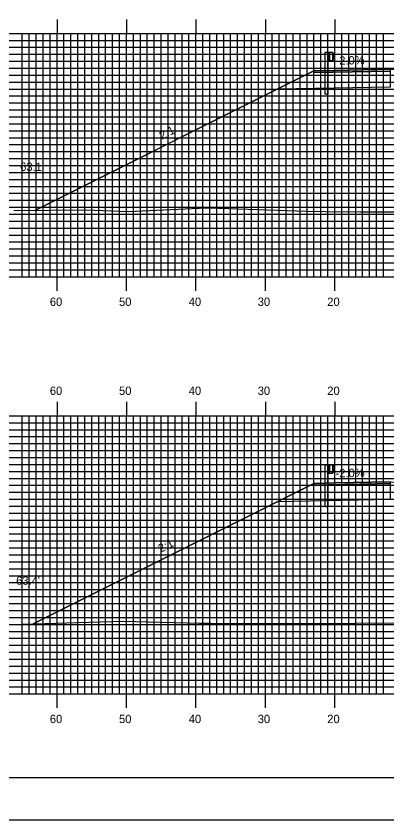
# Model space of a CAD drawing. Extents: x 1812554 to 1812897, y 442591 to 442811.
# Drawn here: x 1812654 to 1812707.4, y 442590.5 to 442706.2 of the extents above; entities that cross this region are included whole.
import ezdxf

# ---------------------------------------------------------------- set-up
doc = ezdxf.new("R2010")
doc.units = 0
for name, color, linetype in [('ANNOTATION', 7, 'Continuous'), ('BORDER', 7, 'Continuous'), ('D_Guardrail_Beam_Lt', 7, 'Continuous'), ('D_Roadway_Centerline', 7, 'Continuous'), ('D_Roadway_Edge_Shoulder', 7, 'Continuous'), ('D_Roadway_SlopeLines', 7, 'Continuous'), ('D_Roadway_SubGrade', 7, 'Continuous'), ('D_Text_Standard', 7, 'Continuous'), ('H_V ANNOTATION', 7, 'Continuous'), ('MAJOR', 7, 'Continuous'), ('MINOR', 7, 'Continuous'), ('PLOT BOUNDARY', 7, 'Continuous'), ('S_Roadway_Centerline', 7, 'Continuous')]:
    doc.layers.add(name, color=color, linetype=linetype)

msp = doc.modelspace()

# ---------------------------------------------------------------- linework, layer by layer
at = {"layer": 'BORDER'}
msp.add_lwpolyline([(1812570.34, 442596.67), (1812890.34, 442596.67), (1812890.34, 442806.67), (1812570.34, 442806.67)], close=True, dxfattribs=at)
at = {"layer": 'D_Guardrail_Beam_Lt'}
for p, q in [((1812698.51, 442700.93), (1812698.51, 442694.93)), ((1812698.98, 442700.93), (1812698.51, 442700.93)), ((1812699.67, 442700.93), (1812698.98, 442700.93)), ((1812698.98, 442700.93), (1812698.98, 442699.76)), ((1812699.05, 442700.93), (1812699.05, 442699.76)), ((1812699.15, 442700.93), (1812699.15, 442699.76)), ((1812699.67, 442699.76), (1812699.67, 442700.93)), ((1812699.67, 442700.84), (1812699.75, 442700.83)), ((1812699.76, 442700.82), (1812699.9, 442700.72)), ((1812698.98, 442699.76), (1812699.67, 442699.76)), ((1812699, 442694.93), (1812699, 442699.76)), ((1812699.75, 442699.86), (1812699.67, 442699.84)), ((1812699.68, 442700.38), (1812699.68, 442700.31)), ((1812699.9, 442700.58), (1812699.71, 442700.44)), ((1812699.71, 442700.25), (1812699.9, 442700.11)), ((1812699.9, 442699.97), (1812699.76, 442699.87)), ((1812699, 442694.93), (1812698.51, 442694.93)), ((1812698.51, 442641.59), (1812698.51, 442635.59)), ((1812698.98, 442641.59), (1812698.51, 442641.59)), ((1812699.67, 442641.59), (1812698.98, 442641.59)), ((1812698.98, 442641.59), (1812698.98, 442640.43)), ((1812699.05, 442641.59), (1812699.05, 442640.43)), ((1812699.15, 442641.59), (1812699.15, 442640.43)), ((1812699.67, 442640.43), (1812699.67, 442641.59)), ((1812699.67, 442641.51), (1812699.75, 442641.49)), ((1812699.75, 442640.52), (1812699.67, 442640.51)), ((1812699.68, 442641.04), (1812699.68, 442640.97)), ((1812699.9, 442641.24), (1812699.71, 442641.11)), ((1812699.71, 442640.91), (1812699.9, 442640.77)), ((1812699.76, 442641.49), (1812699.9, 442641.39)), ((1812699.9, 442640.63), (1812699.76, 442640.53)), ((1812698.98, 442640.43), (1812699.67, 442640.43)), ((1812699, 442635.59), (1812699, 442640.43)), ((1812699, 442635.59), (1812698.51, 442635.59))]:
    msp.add_line(p, q, dxfattribs=at)
for centre, major_axis, start_param, end_param in [((1812699.74, 442700.79), (0.0417, 0), 0.959931, 1.376053), ((1812699.85, 442700.65), (0.0877, 0), 5.323254, 7.243116), ((1812699.75, 442700.38), (-0.0789, 0), 5.323254, 6.283185), ((1812699.75, 442700.31), (-0.0789, 0), 6.283185, 7.243116), ((1812699.74, 442699.9), (0.0417, 0), 4.907132, 5.323254), ((1812699.85, 442700.04), (0.0877, 0), 5.323254, 7.243116), ((1812699.75, 442641.04), (-0.0789, 0), 5.323254, 6.283185), ((1812699.75, 442640.97), (-0.0789, 0), 6.283185, 7.243116), ((1812699.74, 442641.45), (0.0417, 0), 0.959931, 1.376053), ((1812699.74, 442640.56), (0.0417, 0), 4.907132, 5.323254), ((1812699.85, 442641.32), (0.0877, 0), 5.323254, 7.243116), ((1812699.85, 442640.7), (0.0877, 0), 5.323254, 7.243116)]:
    msp.add_ellipse(centre, major_axis=major_axis, ratio=0.995501, start_param=start_param, end_param=end_param, dxfattribs=at)
at = {"layer": 'D_Roadway_Centerline'}
for points in [[(1812656.82, 442678.23), (1812691.73, 442695.68), (1812696.94, 442698.28), (1812699.94, 442698.34), (1812707.94, 442698.5), (1812719.94, 442697.93), (1812731.94, 442697.35), (1812739.94, 442696.97), (1812742.94, 442696.82), (1812748.47, 442694.06), (1812784.48, 442676.06)], [(1812656.53, 442618.74), (1812691.73, 442636.34), (1812696.94, 442638.95), (1812699.94, 442639.01), (1812707.94, 442639.17), (1812719.94, 442638.59), (1812731.94, 442638.02), (1812739.94, 442637.63), (1812742.94, 442637.49), (1812748.47, 442634.72), (1812777.24, 442620.34)]]:
    msp.add_lwpolyline(points, dxfattribs=at)
at = {"layer": 'D_Roadway_Edge_Shoulder'}
for points in [[(1812707.94, 442698.5), (1812699.94, 442698.34), (1812699.94, 442698.34), (1812696.94, 442698.28), (1812696.94, 442698.03), (1812707.94, 442698.25)], [(1812707.94, 442639.17), (1812699.94, 442639.01), (1812699.94, 442639.01), (1812696.94, 442638.95), (1812696.94, 442638.7), (1812707.94, 442638.92)]]:
    msp.add_lwpolyline(points, close=True, dxfattribs=at)
at = {"layer": 'D_Roadway_SlopeLines'}
for points in [[(1812696.94, 442698.28), (1812656.82, 442678.23)], [(1812696.94, 442638.95), (1812656.53, 442618.74)]]:
    msp.add_lwpolyline(points, dxfattribs=at)
at = {"layer": 'D_Roadway_SubGrade'}
for points in [[(1812707.94, 442697.84), (1812707.94, 442698.25), (1812696.94, 442698.03), (1812696.94, 442698.28), (1812691.73, 442695.68), (1812707.94, 442696)], [(1812707.94, 442638.5), (1812707.94, 442638.92), (1812696.94, 442638.7), (1812696.94, 442638.95), (1812691.73, 442636.34), (1812707.94, 442636.67)]]:
    msp.add_lwpolyline(points, close=True, dxfattribs=at)
at = {"layer": 'MAJOR'}
for p, q in [((1812659.94, 442705.67), (1812659.94, 442703.67)), ((1812669.94, 442705.67), (1812669.94, 442703.67)), ((1812679.94, 442705.67), (1812679.94, 442703.67)), ((1812689.94, 442705.67), (1812689.94, 442703.67)), ((1812699.94, 442705.67), (1812699.94, 442703.67)), ((1812579.94, 442703.67), (1812859.94, 442703.67)), ((1812579.94, 442703.67), (1812859.94, 442703.67)), ((1812659.94, 442668.67), (1812659.94, 442703.67)), ((1812669.94, 442668.67), (1812669.94, 442703.67)), ((1812679.94, 442668.67), (1812679.94, 442703.67)), ((1812689.94, 442668.67), (1812689.94, 442703.67)), ((1812699.94, 442668.67), (1812699.94, 442703.67)), ((1812579.94, 442698.67), (1812859.94, 442698.67)), ((1812579.94, 442693.67), (1812859.94, 442693.67)), ((1812579.94, 442688.67), (1812859.94, 442688.67)), ((1812579.94, 442683.67), (1812859.94, 442683.67)), ((1812579.94, 442678.67), (1812859.94, 442678.67)), ((1812579.94, 442673.67), (1812859.94, 442673.67)), ((1812579.94, 442668.67), (1812859.94, 442668.67)), ((1812579.94, 442668.67), (1812859.94, 442668.67)), ((1812659.94, 442666.66), (1812659.94, 442668.67)), ((1812669.94, 442666.66), (1812669.94, 442668.67)), ((1812679.94, 442666.66), (1812679.94, 442668.67)), ((1812689.94, 442666.66), (1812689.94, 442668.67)), ((1812699.94, 442666.66), (1812699.94, 442668.67)), ((1812659.94, 442650.67), (1812659.94, 442648.67)), ((1812669.94, 442650.67), (1812669.94, 442648.67)), ((1812679.94, 442650.67), (1812679.94, 442648.67)), ((1812689.94, 442650.67), (1812689.94, 442648.67)), ((1812699.94, 442650.67), (1812699.94, 442648.67)), ((1812579.94, 442648.67), (1812859.94, 442648.67)), ((1812579.94, 442648.67), (1812859.94, 442648.67)), ((1812659.94, 442608.67), (1812659.94, 442648.67)), ((1812669.94, 442608.67), (1812669.94, 442648.67)), ((1812679.94, 442608.67), (1812679.94, 442648.67)), ((1812689.94, 442608.67), (1812689.94, 442648.67)), ((1812699.94, 442608.67), (1812699.94, 442648.67)), ((1812579.94, 442643.67), (1812859.94, 442643.67)), ((1812579.94, 442638.67), (1812859.94, 442638.67)), ((1812579.94, 442633.67), (1812859.94, 442633.67)), ((1812579.94, 442628.67), (1812859.94, 442628.67)), ((1812579.94, 442623.67), (1812859.94, 442623.67)), ((1812579.94, 442618.67), (1812859.94, 442618.67)), ((1812579.94, 442613.67), (1812859.94, 442613.67)), ((1812579.94, 442608.67), (1812859.94, 442608.67)), ((1812579.94, 442608.67), (1812859.94, 442608.67)), ((1812659.94, 442606.66), (1812659.94, 442608.67)), ((1812669.94, 442606.66), (1812669.94, 442608.67)), ((1812679.94, 442606.66), (1812679.94, 442608.67)), ((1812689.94, 442606.66), (1812689.94, 442608.67)), ((1812699.94, 442606.66), (1812699.94, 442608.67))]:
    msp.add_line(p, q, dxfattribs=at)
at = {"layer": 'MINOR'}
for p, q in [((1812654.94, 442668.67), (1812654.94, 442703.67)), ((1812655.94, 442668.67), (1812655.94, 442703.67)), ((1812656.94, 442668.67), (1812656.94, 442703.67)), ((1812657.94, 442668.67), (1812657.94, 442703.67)), ((1812658.94, 442668.67), (1812658.94, 442703.67)), ((1812660.94, 442668.67), (1812660.94, 442703.67)), ((1812661.94, 442668.67), (1812661.94, 442703.67)), ((1812662.94, 442668.67), (1812662.94, 442703.67)), ((1812663.94, 442668.67), (1812663.94, 442703.67)), ((1812664.94, 442668.67), (1812664.94, 442703.67)), ((1812665.94, 442668.67), (1812665.94, 442703.67)), ((1812666.94, 442668.67), (1812666.94, 442703.67)), ((1812667.94, 442668.67), (1812667.94, 442703.67)), ((1812668.94, 442668.67), (1812668.94, 442703.67)), ((1812670.94, 442668.67), (1812670.94, 442703.67)), ((1812671.94, 442668.67), (1812671.94, 442703.67)), ((1812672.94, 442668.67), (1812672.94, 442703.67)), ((1812673.94, 442668.67), (1812673.94, 442703.67)), ((1812674.94, 442668.67), (1812674.94, 442703.67)), ((1812675.94, 442668.67), (1812675.94, 442703.67)), ((1812676.94, 442668.67), (1812676.94, 442703.67)), ((1812677.94, 442668.67), (1812677.94, 442703.67)), ((1812678.94, 442668.67), (1812678.94, 442703.67)), ((1812680.94, 442668.67), (1812680.94, 442703.67)), ((1812681.94, 442668.67), (1812681.94, 442703.67)), ((1812682.94, 442668.67), (1812682.94, 442703.67)), ((1812683.94, 442668.67), (1812683.94, 442703.67)), ((1812684.94, 442668.67), (1812684.94, 442703.67)), ((1812685.94, 442668.67), (1812685.94, 442703.67)), ((1812686.94, 442668.67), (1812686.94, 442703.67)), ((1812687.94, 442668.67), (1812687.94, 442703.67)), ((1812688.94, 442668.67), (1812688.94, 442703.67)), ((1812690.94, 442668.67), (1812690.94, 442703.67)), ((1812691.94, 442668.67), (1812691.94, 442703.67)), ((1812692.94, 442668.67), (1812692.94, 442703.67)), ((1812693.94, 442668.67), (1812693.94, 442703.67)), ((1812694.94, 442668.67), (1812694.94, 442703.67)), ((1812695.94, 442668.67), (1812695.94, 442703.67)), ((1812696.94, 442668.67), (1812696.94, 442703.67)), ((1812697.94, 442668.67), (1812697.94, 442703.67)), ((1812698.94, 442668.67), (1812698.94, 442703.67)), ((1812700.94, 442668.67), (1812700.94, 442703.67)), ((1812701.94, 442668.67), (1812701.94, 442703.67)), ((1812702.94, 442668.67), (1812702.94, 442703.67)), ((1812703.94, 442668.67), (1812703.94, 442703.67)), ((1812704.94, 442668.67), (1812704.94, 442703.67)), ((1812705.94, 442668.67), (1812705.94, 442703.67)), ((1812706.94, 442668.67), (1812706.94, 442703.67)), ((1812579.94, 442702.67), (1812859.94, 442702.67)), ((1812579.94, 442701.67), (1812859.94, 442701.67)), ((1812579.94, 442700.67), (1812859.94, 442700.67)), ((1812579.94, 442699.67), (1812859.94, 442699.67)), ((1812579.94, 442697.67), (1812859.94, 442697.67)), ((1812579.94, 442696.67), (1812859.94, 442696.67)), ((1812579.94, 442695.67), (1812859.94, 442695.67)), ((1812579.94, 442694.67), (1812859.94, 442694.67)), ((1812579.94, 442692.67), (1812859.94, 442692.67)), ((1812579.94, 442691.67), (1812859.94, 442691.67)), ((1812579.94, 442690.67), (1812859.94, 442690.67)), ((1812579.94, 442689.67), (1812859.94, 442689.67)), ((1812579.94, 442687.67), (1812859.94, 442687.67)), ((1812579.94, 442686.67), (1812859.94, 442686.67)), ((1812579.94, 442685.67), (1812859.94, 442685.67)), ((1812579.94, 442684.67), (1812859.94, 442684.67)), ((1812579.94, 442682.67), (1812859.94, 442682.67)), ((1812579.94, 442681.67), (1812859.94, 442681.67)), ((1812579.94, 442680.67), (1812859.94, 442680.67)), ((1812579.94, 442679.67), (1812859.94, 442679.67)), ((1812579.94, 442677.67), (1812859.94, 442677.67)), ((1812579.94, 442676.67), (1812859.94, 442676.67)), ((1812579.94, 442675.67), (1812859.94, 442675.67)), ((1812579.94, 442674.67), (1812859.94, 442674.67)), ((1812579.94, 442672.67), (1812859.94, 442672.67)), ((1812579.94, 442671.67), (1812859.94, 442671.67)), ((1812579.94, 442670.67), (1812859.94, 442670.67)), ((1812579.94, 442669.67), (1812859.94, 442669.67)), ((1812654.94, 442608.67), (1812654.94, 442648.67)), ((1812655.94, 442608.67), (1812655.94, 442648.67)), ((1812656.94, 442608.67), (1812656.94, 442648.67)), ((1812657.94, 442608.67), (1812657.94, 442648.67)), ((1812658.94, 442608.67), (1812658.94, 442648.67)), ((1812660.94, 442608.67), (1812660.94, 442648.67)), ((1812661.94, 442608.67), (1812661.94, 442648.67)), ((1812662.94, 442608.67), (1812662.94, 442648.67)), ((1812663.94, 442608.67), (1812663.94, 442648.67)), ((1812664.94, 442608.67), (1812664.94, 442648.67)), ((1812665.94, 442608.67), (1812665.94, 442648.67)), ((1812666.94, 442608.67), (1812666.94, 442648.67)), ((1812667.94, 442608.67), (1812667.94, 442648.67)), ((1812668.94, 442608.67), (1812668.94, 442648.67)), ((1812670.94, 442608.67), (1812670.94, 442648.67)), ((1812671.94, 442608.67), (1812671.94, 442648.67)), ((1812672.94, 442608.67), (1812672.94, 442648.67)), ((1812673.94, 442608.67), (1812673.94, 442648.67)), ((1812674.94, 442608.67), (1812674.94, 442648.67)), ((1812675.94, 442608.67), (1812675.94, 442648.67)), ((1812676.94, 442608.67), (1812676.94, 442648.67)), ((1812677.94, 442608.67), (1812677.94, 442648.67)), ((1812678.94, 442608.67), (1812678.94, 442648.67)), ((1812680.94, 442608.67), (1812680.94, 442648.67)), ((1812681.94, 442608.67), (1812681.94, 442648.67)), ((1812682.94, 442608.67), (1812682.94, 442648.67)), ((1812683.94, 442608.67), (1812683.94, 442648.67)), ((1812684.94, 442608.67), (1812684.94, 442648.67)), ((1812685.94, 442608.67), (1812685.94, 442648.67)), ((1812686.94, 442608.67), (1812686.94, 442648.67)), ((1812687.94, 442608.67), (1812687.94, 442648.67)), ((1812688.94, 442608.67), (1812688.94, 442648.67)), ((1812690.94, 442608.67), (1812690.94, 442648.67)), ((1812691.94, 442608.67), (1812691.94, 442648.67)), ((1812692.94, 442608.67), (1812692.94, 442648.67)), ((1812693.94, 442608.67), (1812693.94, 442648.67)), ((1812694.94, 442608.67), (1812694.94, 442648.67)), ((1812695.94, 442608.67), (1812695.94, 442648.67)), ((1812696.94, 442608.67), (1812696.94, 442648.67)), ((1812697.94, 442608.67), (1812697.94, 442648.67)), ((1812698.94, 442608.67), (1812698.94, 442648.67)), ((1812700.94, 442608.67), (1812700.94, 442648.67)), ((1812701.94, 442608.67), (1812701.94, 442648.67)), ((1812702.94, 442608.67), (1812702.94, 442648.67)), ((1812703.94, 442608.67), (1812703.94, 442648.67)), ((1812704.94, 442608.67), (1812704.94, 442648.67)), ((1812705.94, 442608.67), (1812705.94, 442648.67)), ((1812706.94, 442608.67), (1812706.94, 442648.67)), ((1812579.94, 442647.67), (1812859.94, 442647.67)), ((1812579.94, 442646.67), (1812859.94, 442646.67)), ((1812579.94, 442645.67), (1812859.94, 442645.67)), ((1812579.94, 442644.67), (1812859.94, 442644.67)), ((1812579.94, 442642.67), (1812859.94, 442642.67)), ((1812579.94, 442641.67), (1812859.94, 442641.67)), ((1812579.94, 442640.67), (1812859.94, 442640.67)), ((1812579.94, 442639.67), (1812859.94, 442639.67)), ((1812579.94, 442637.67), (1812859.94, 442637.67)), ((1812579.94, 442636.67), (1812859.94, 442636.67)), ((1812579.94, 442635.67), (1812859.94, 442635.67)), ((1812579.94, 442634.67), (1812859.94, 442634.67)), ((1812579.94, 442632.67), (1812859.94, 442632.67)), ((1812579.94, 442631.67), (1812859.94, 442631.67)), ((1812579.94, 442630.67), (1812859.94, 442630.67)), ((1812579.94, 442629.67), (1812859.94, 442629.67)), ((1812579.94, 442627.67), (1812859.94, 442627.67)), ((1812579.94, 442626.67), (1812859.94, 442626.67)), ((1812579.94, 442625.67), (1812859.94, 442625.67)), ((1812579.94, 442624.67), (1812859.94, 442624.67)), ((1812579.94, 442622.67), (1812859.94, 442622.67)), ((1812579.94, 442621.67), (1812859.94, 442621.67)), ((1812579.94, 442620.67), (1812859.94, 442620.67)), ((1812579.94, 442619.67), (1812859.94, 442619.67)), ((1812579.94, 442617.67), (1812859.94, 442617.67)), ((1812579.94, 442616.67), (1812859.94, 442616.67)), ((1812579.94, 442615.67), (1812859.94, 442615.67)), ((1812579.94, 442614.67), (1812859.94, 442614.67)), ((1812579.94, 442612.67), (1812859.94, 442612.67)), ((1812579.94, 442611.67), (1812859.94, 442611.67)), ((1812579.94, 442610.67), (1812859.94, 442610.67)), ((1812579.94, 442609.67), (1812859.94, 442609.67))]:
    msp.add_line(p, q, dxfattribs=at)
at = {"layer": 'PLOT BOUNDARY'}
msp.add_lwpolyline([(1812554.16, 442590.55), (1812894.16, 442590.55), (1812894.16, 442810.55), (1812554.16, 442810.55)], close=True, dxfattribs=at)
at = {"layer": 'S_Roadway_Centerline'}
for points in [[(1812653.73, 442678.2), (1812664.05, 442678.28), (1812670.2, 442678.03), (1812681.46, 442678.56), (1812681.74, 442678.57), (1812683.25, 442678.52), (1812695.85, 442678.12), (1812698.51, 442678.03), (1812703.64, 442678.01), (1812716.05, 442678), (1812721.43, 442677.84), (1812732.8, 442678.11), (1812733.7, 442678.15), (1812737.73, 442677.96), (1812747.15, 442677.59), (1812749.41, 442677.36), (1812761.79, 442677.03), (1812767.82, 442676.93), (1812779.87, 442676.18)], [(1812650.1, 442618.55), (1812669.43, 442619.14), (1812680.46, 442618.84), (1812682.07, 442618.84), (1812698.91, 442618.79), (1812706.9, 442618.91), (1812714.95, 442618.78), (1812720.34, 442618.78), (1812731.14, 442619.09), (1812732.66, 442619.12), (1812733.73, 442619.12), (1812750.36, 442619.27), (1812757.81, 442619.39), (1812767.9, 442620.07), (1812770.37, 442620.21), (1812780.84, 442620.41)]]:
    msp.add_lwpolyline(points, dxfattribs=at)

# ---------------------------------------------------------------- texts
at = {"layer": 'ANNOTATION'}
for s, rotation, p in [('-2.0%', 1.1458, (1812700.05, 442699.15)), ('2:1', 26.5651, (1812675.03, 442688.36)), ('-2.0%', 1.1458, (1812700.05, 442639.81)), ('2:1', 26.5651, (1812674.88, 442628.96))]:
    msp.add_text(s, height=1.2, rotation=rotation, dxfattribs=at).set_placement(p)
at = {"layer": 'D_Text_Standard'}
for s, p in [("63.1'", (1812654.64, 442683.89)), ("63.4'", (1812654.06, 442624.37))]:
    msp.add_text(s, height=1.2, dxfattribs=at).set_placement(p)
at = {"layer": 'H_V ANNOTATION'}
for s, p in [('60', (1812658.91, 442664.47)), ('50', (1812668.87, 442664.47)), ('40', (1812678.91, 442664.47)), ('30', (1812688.84, 442664.47)), ('20', (1812698.85, 442664.47)), ('60', (1812658.91, 442651.67)), ('50', (1812668.87, 442651.67)), ('40', (1812678.91, 442651.67)), ('30', (1812688.84, 442651.67)), ('20', (1812698.85, 442651.67)), ('60', (1812658.91, 442604.47)), ('50', (1812668.87, 442604.47)), ('40', (1812678.91, 442604.47)), ('30', (1812688.84, 442604.47)), ('20', (1812698.85, 442604.47))]:
    msp.add_text(s, height=1.2, dxfattribs=at).set_placement(p)

doc.saveas('drawing.dxf')
